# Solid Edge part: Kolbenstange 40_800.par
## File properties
Username: ahadarics
Dokumentum tartalom típus: 0
Author: ahadarics
Last saved by: ahadarics
Revision: 97
Sűrűség: 0,000 kg/m^3
Pontosság: 0,990
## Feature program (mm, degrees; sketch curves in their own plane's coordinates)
base feature "unnamed BaseFeature 1"
thread "unnamed Thread 1"
chamfer "Letörés_1"  SetBackValue2 = 20 deg
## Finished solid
Body 1: solid body, 21 faces, 32 edges, 14 vertices.
  Faces by surface: plane 8, cylinder 5, cone 4, torus 4
  Edges by curve: circle 17, line 9, curve on surface 4, ellipse 2
Bounding box of the edges (mm; curved faces can reach further): 40.000 x 40.000 x 928.000, from (-20, -20, -78) to (20, 20, 850).
Cylindrical faces by radius (mm): R5 x1, R6 x1, R7.75 x1, R8 x1, R20 x1
Conical faces (half-angle, radius in mm at the cone's reference point): 20 deg R6 x1, 30 deg R7.875 x1, 45 deg R19.6 x1, 60 deg R5.5 x1
Toroidal faces (ring radius, tube radius in mm): R5.4 r0.4 x2, R6.55 r1.2 x2
Planar faces by outward normal: +x 1, +z 3, -x 1, -z 1, oblique 2
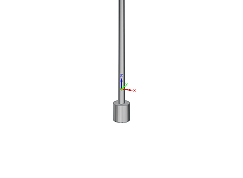
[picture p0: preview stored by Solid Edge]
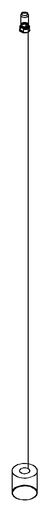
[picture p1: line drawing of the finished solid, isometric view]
